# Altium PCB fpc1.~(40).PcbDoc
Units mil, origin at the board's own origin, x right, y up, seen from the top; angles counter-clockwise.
Board outline 3523.62 x 288.66 mil, 2 copper layers (Top Layer, Bottom Layer), stack 1.929 mil thick; 5 components, 5 nets, 20 pads, 5 vias.
Unrouted connection lines stored in the file: 6.
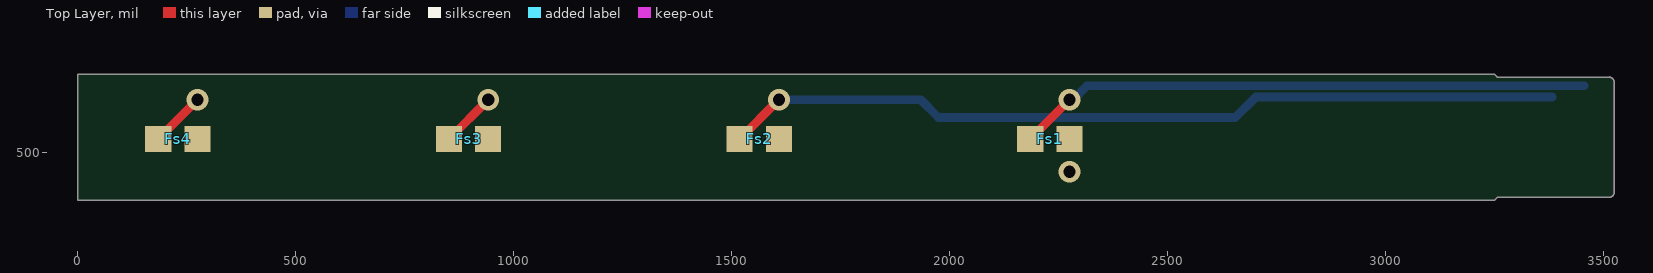
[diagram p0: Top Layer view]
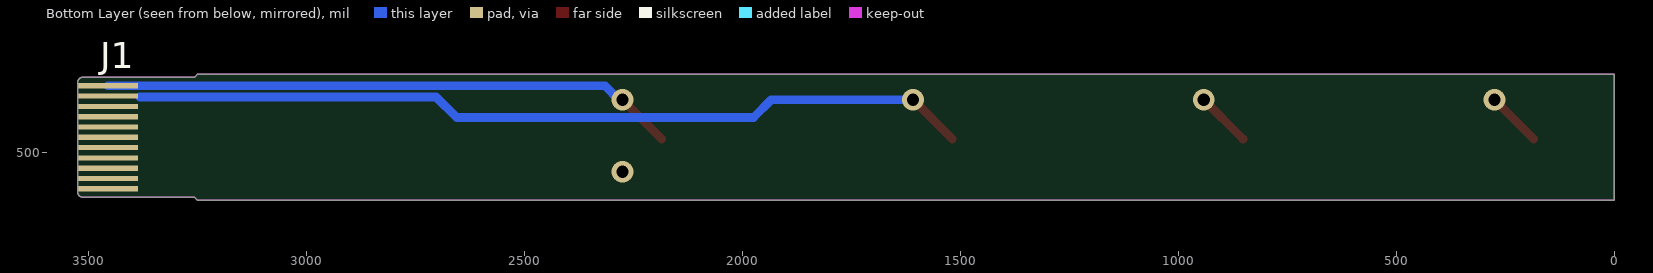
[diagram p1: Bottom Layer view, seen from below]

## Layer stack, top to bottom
Top Solder: solder mask 0.4, Solder Resist, Dk 3.5
Top Layer: signal copper 0.4724
Dielectric 1: dielectric 0.9843, FR-4, Dk 4.8
Bottom Layer: signal copper 0.4724
Bottom Solder: solder mask 0.4, Solder Resist, Dk 3.5

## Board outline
0.5,389.5 0.5,678.16 3249.87,678.16 3256.41,671.63 3512.31,671.63 cw(c3512.31,659.82) 3524.12,659.82 3524.12,407.85 cw(c3512.31,407.85) 3512.31,396.04 3256.41,396.04 3249.87,389.5

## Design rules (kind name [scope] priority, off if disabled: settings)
Clearance [All] p1: gap=3 ignorepadtopadclearanceinfootprint=TRUE except(0: Arc-Hole Track-Hole SMDPad-Hole THPad-Hole Via-Hole Fill-Hole Poly-Hole Region-Hole Text-Hole)
DiffPairsRouting [All] p1: maxlimit=10 minlimit=10 mostfreqgap=10 toplayer_minwidth=15 toplayer_maxwidth=15 toplayer_prefwidth=15 bottomlayer_minwidth=15 bottomlayer_maxwidth=15 bottomlayer_prefwidth=15 substack1={6BAC4FC8-8DE6-4E41-AF8A-9441F3E19743} toplayer_{6bac4fc8-8de6-4e41-af8a-9441f3e19743}_minwidth=15 toplayer_{6bac4fc8-8de6-4e41-af8a-9441f3e19743}_maxwidth=15 toplayer_{6bac4fc8-8de6-4e41-af8a-9441f3e19743}_prefwidth=15 bottomlayer_{6bac4fc8-8de6-4e41-af8a-9441f3e19743}_minwidth=15 bottomlayer_{6bac4fc8-8de6-4e41-af8a-9441f3e19743}_maxwidth=15 bottomlayer_{6bac4fc8-8de6-4e41-af8a-9441f3e19743}_prefwidth=15 maxuncoupledlength=500
PolygonConnect [All] p1: connectstyle=Relief reliefconductorwidth=10 reliefentries=4 polygonreliefangle="90 Angle" airgapwidth=10
RoutingVias [All] p1: holewidth=28 width=50 viastyle="Through Hole" minholewidth=28 minwidth=50 maxholewidth=28 maxwidth=50
SolderMaskExpansion [All] p1: expansion=4 istentingtop=FALSE
Width [All] p1: maxlimit=20 minlimit=10 preferedwidth=15 substack1={6BAC4FC8-8DE6-4E41-AF8A-9441F3E19743} toplayer_{6bac4fc8-8de6-4e41-af8a-9441f3e19743}_maxwidth=10 toplayer_{6bac4fc8-8de6-4e41-af8a-9441f3e19743}_prefwidth=10 bottomlayer_{6bac4fc8-8de6-4e41-af8a-9441f3e19743}_maxwidth=10 bottomlayer_{6bac4fc8-8de6-4e41-af8a-9441f3e19743}_prefwidth=10 minimp=50.000000 maximp=50.000000 favimp=50.000000
29 further rules are at their usual default settings.

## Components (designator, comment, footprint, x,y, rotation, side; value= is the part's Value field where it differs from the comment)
Fs1 "ForceSensor" sensor_connector 2230,530 r0 top
Fs2 "ForceSensor" sensor_connector 1563.33,530 r0 top
Fs3 "ForceSensor" sensor_connector 896.67,530 r0 top
Fs4 "ForceSensor" sensor_connector 230,530 r0 top
J1 "FPC_connector" FPC_connector 3454.72,533.82 r180 bottom

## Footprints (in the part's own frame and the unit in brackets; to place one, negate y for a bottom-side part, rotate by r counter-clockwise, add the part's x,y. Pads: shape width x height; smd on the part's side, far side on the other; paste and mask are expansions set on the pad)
FPC_connector [mm]
  rect 3.5x0.3 smd: 0(0,3) 1(0,3) 2(0,2.4) 3(0,1.8) 4(0,1.2) 5(0,0.6) 6(0,0) 7(0,-0.6) 8(0,-1.2) 9(0,-1.8) 10(0,-2.4) 11(0,-3)
sensor_connector [mil]
  rect 60x60 smd: 0(-45,0) 1(45,0)

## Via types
v1: diameter 50, hole 28, Top Layer to Bottom Layer, 5 vias

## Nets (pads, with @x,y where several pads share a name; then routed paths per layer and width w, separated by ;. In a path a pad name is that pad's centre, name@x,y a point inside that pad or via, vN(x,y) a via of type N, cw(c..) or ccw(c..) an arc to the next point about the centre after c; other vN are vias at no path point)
FS1: Fs1.0 J1.1 | length 1320.2
  Top Layer w20: Fs1.0 v1(2275,620)
  Bottom Layer w20: v1(2275,620) 2283.12,620 2315.05,651.93 J1.1
FS2: Fs2.0 J1.2 | length 1937.3
  Top Layer w20: Fs2.0 v1(1608.33,620)
  Bottom Layer w20: v1(1608.33,620) 1933.74,620 1974.65,579.09 2654.85,579.09 2701.78,626.02 3381.98,626.02
FS3: Fs3.0 J1.3 | length 127.3
  Top Layer w20: Fs3.0 v1(941.67,620)
FS4: Fs4.0 J1.4 | length 127.3
  Top Layer w20: Fs4.0 v1(275,620)
GND: Fs1.1 Fs2.1 Fs3.1 Fs4.1 J1.0
pads on no net: J1.5 J1.6 J1.7 J1.8 J1.9 J1.10 J1.11
copper on no net:
  other v1: 2275,455

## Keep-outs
Keep-Out Layer:
  the board outline again, w0.5

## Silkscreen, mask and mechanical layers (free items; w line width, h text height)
Board Shape:
  the board outline again, w0.5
